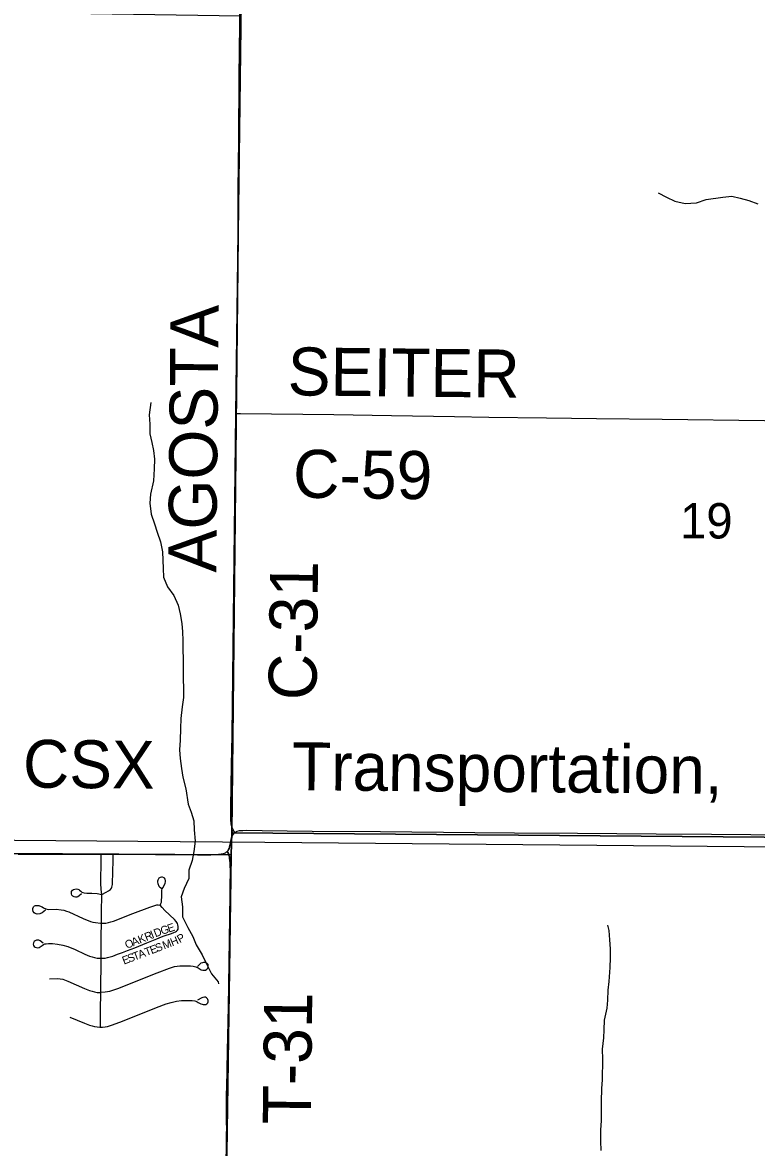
# Model space of a CAD drawing. Extents: x 1584893 to 1934202, y 663575 to 1091909.
# Drawn here: x 1743487 to 1748072, y 941008 to 948034 of the extents above; entities that cross this region are included whole.
import ezdxf

# ---------------------------------------------------------------- set-up
doc = ezdxf.new("R2010")
doc.units = 0
for name, color, linetype in [('GM_X_City_Street', 7, 'Continuous'), ('GM_X_City_Street_Text', 7, 'Continuous'), ('GM_X_Corporation', 7, 'Continuous'), ('GM_X_County_Road', 7, 'Continuous'), ('GM_X_County_Road_Text', 7, 'Continuous'), ('GM_X_Minor_River', 7, 'Continuous'), ('GM_X_Rail_Line', 7, 'Continuous'), ('GM_X_Rail_Line_Text', 7, 'Continuous'), ('GM_X_Section', 7, 'Continuous'), ('GM_X_Section_Text', 7, 'Continuous'), ('GM_X_State_Route', 7, 'Continuous'), ('GM_X_Township', 7, 'Continuous'), ('GM_X_Township_Road', 7, 'Continuous'), ('GM_X_Township_Road_Text', 7, 'Continuous')]:
    doc.layers.add(name, color=color, linetype=linetype)

msp = doc.modelspace()

# ---------------------------------------------------------------- linework, layer by layer
at = {"layer": 'GM_X_City_Street'}
for points in [[(1743982.7, 942587.2), (1743978.7, 942619.5), (1743977.2, 942658.5), (1743977.9, 942804.1), (1743978, 942841.4)], [(1743982.7, 942587.2), (1744009.9, 942601.6), (1744024.1, 942610.4), (1744031.2, 942615.2), (1744036.9, 942620), (1744042.5, 942627.1), (1744045.2, 942634), (1744047.4, 942642.1), (1744049.4, 942649.8), (1744050.5, 942666.1), (1744052.5, 942716.5), (1744052.9, 942813.3), (1744053.1, 942840.6)], [(1744348, 942521.8), (1744352.3, 942531.6), (1744355.2, 942541), (1744356.5, 942555.4), (1744356.9, 942569), (1744357.5, 942598.2), (1744358.1, 942614.6), (1744360.3, 942623.4), (1744363.5, 942629.8), (1744372.6, 942643.7), (1744378.9, 942658.8), (1744380.2, 942666.7), (1744380.2, 942674.8), (1744378.1, 942684.1), (1744375.1, 942689.2), (1744371.3, 942691.7), (1744362, 942695.2), (1744354.7, 942695.6), (1744347.5, 942694.3), (1744339.9, 942689.2), (1744334.3, 942681.5), (1744331.8, 942676.5), (1744330.5, 942671.3), (1744331, 942664.6), (1744333, 942656.5), (1744339.6, 942640.9), (1744346, 942634.6), (1744354.6, 942628.3)], [(1743856.9, 942592.7), (1743842, 942579.3), (1743833.1, 942574.3), (1743825.9, 942571.8), (1743818.7, 942571.8), (1743809.3, 942574.3), (1743801.7, 942577.3), (1743795.3, 942584.5), (1743793.2, 942591.3), (1743793.2, 942598.8), (1743794.4, 942607.5), (1743799.1, 942614.7), (1743805.5, 942618.9), (1743814.4, 942621.9), (1743822.9, 942622.8), (1743832.2, 942621.9), (1743839, 942618.5), (1743844.1, 942614.3), (1743851.4, 942608), (1743857.5, 942603.6), (1743864.5, 942600.3), (1743872.4, 942597.5), (1743888.4, 942596.1), (1743921, 942595.3), (1743953, 942593.2), (1743982.7, 942587.2)], [(1743980.6, 942409), (1743981.8, 942475.9), (1743982.7, 942587.2)], [(1743630.6, 942490.9), (1743610.5, 942474.4), (1743595.2, 942468.1), (1743578.7, 942465.9), (1743567.2, 942468.5), (1743560, 942473.1), (1743554.9, 942481.6), (1743552.7, 942492.3), (1743552.7, 942501.6), (1743556.1, 942511.4), (1743562.1, 942517.8), (1743568.5, 942519.5), (1743576.5, 942520.3), (1743588.8, 942519.9), (1743603.8, 942513.5), (1743609.2, 942510.1), (1743617.6, 942504.5), (1743632.2, 942497.6), (1743648.2, 942495.3), (1743697.3, 942495.4), (1743729.8, 942492.6), (1743745.8, 942489.5), (1743761.4, 942484.9), (1743776.6, 942479.1), (1743865.6, 942438), (1743911.2, 942420.3), (1743926.9, 942415.8), (1743942.9, 942412.6), (1743975.4, 942409.1), (1743980.6, 942409)], [(1743978, 942189.9), (1743986.8, 942189.8), (1744003.1, 942191.1), (1744019.3, 942193.9), (1744050.9, 942203.2), (1744081.6, 942214.4), (1744111.5, 942225.6), (1744143.3, 942238), (1744188.6, 942255.8), (1744265, 942286.2), (1744325.7, 942311.2), (1744356, 942323.8), (1744371.5, 942329.3), (1744418.3, 942345), (1744433.6, 942351.2), (1744442, 942354.9), (1744449.2, 942359.6), (1744455.5, 942365.1), (1744459.8, 942372.3), (1744460.6, 942380.8), (1744459.7, 942388.9), (1744458.5, 942399.1), (1744455.1, 942406.3), (1744451.3, 942412.7), (1744446.9, 942418.9), (1744436, 942431.3), (1744377.4, 942489), (1744360.3, 942507.8), (1744348, 942521.8)], [(1743980.6, 942409), (1743991.7, 942408.8), (1744008, 942409.7), (1744024.1, 942412.1), (1744039.8, 942416.3), (1744055.2, 942421.8), (1744177.1, 942468.6), (1744283, 942508.2), (1744314.8, 942519.6), (1744326.3, 942522.7), (1744335.7, 942523.1), (1744348, 942521.8)], [(1743978, 942189.9), (1743978, 942194.6), (1743979.1, 942327), (1743980.6, 942409)], [(1743617.3, 942283.4), (1743597.3, 942299.1), (1743589.3, 942302), (1743581.5, 942303.3), (1743574.5, 942303.2), (1743565.9, 942299.2), (1743560, 942294.7), (1743555.8, 942287.1), (1743554.5, 942277.7), (1743556.7, 942269.2), (1743560.9, 942262.5), (1743567.5, 942258.4), (1743574.5, 942256.1), (1743583.3, 942255.6), (1743591.9, 942257.8), (1743598.4, 942261.7), (1743609.7, 942270.5), (1743618.8, 942276.3), (1743626.3, 942279), (1743635.2, 942280.7), (1743649.7, 942282), (1743674.1, 942281.4), (1743706.9, 942277.9), (1743739.2, 942271.8), (1743770.6, 942262.3), (1743816.3, 942243.9), (1743875.8, 942215.7), (1743906.2, 942203.1), (1743921.7, 942197.7), (1743937.6, 942193.7), (1743953.9, 942191.4), (1743970.3, 942190), (1743978, 942189.9)], [(1743977, 941977.1), (1743977.1, 941979.2), (1743978, 942189.9)], [(1743977, 941977.1), (1744003.9, 941979.3), (1744032.5, 941984.3), (1744052.2, 941989.7), (1744083.2, 942001.2), (1744328.9, 942098.9), (1744406.1, 942128.2), (1744437.7, 942137.6), (1744453.9, 942140.6), (1744470.3, 942142.4), (1744503.4, 942143.1), (1744536.5, 942141.9), (1744552.9, 942140.2), (1744569, 942136.7), (1744583.8, 942129.7), (1744598, 942121), (1744604.3, 942117.9), (1744613.4, 942115.4), (1744622.6, 942115.4), (1744631.1, 942116.2), (1744639.1, 942120.9), (1744645.1, 942127.2), (1744647.2, 942134.9), (1744648, 942142.6), (1744646.3, 942151.5), (1744641.7, 942157.9), (1744633.2, 942162.1), (1744626, 942163.1), (1744618.3, 942162.9), (1744611.1, 942161.2), (1744602.2, 942158.3), (1744580.3, 942139.4)], [(1743656.8, 942060.5), (1743706.3, 942062.7), (1743722.7, 942061.7), (1743738.7, 942058.3), (1743769.8, 942047.5), (1743875.6, 942000.4), (1743906.4, 941988.4), (1743922.1, 941983.4), (1743938.1, 941979.2), (1743954.4, 941976.9), (1743970.9, 941976.5), (1743977, 941977.1)], [(1743974.9, 941760.5), (1743975, 941770.2), (1743975.4, 941863.2), (1743977, 941977.1)], [(1743974.9, 941760.5), (1743986.5, 941760.4), (1744002.8, 941761.8), (1744018.9, 941764.6), (1744050.4, 941773.4), (1744111.8, 941796.1), (1744324, 941882.7), (1744385.4, 941905.3), (1744416.8, 941914.3), (1744448.8, 941921.1), (1744481.3, 941925.3), (1744514, 941927), (1744546.7, 941925.8), (1744562.9, 941923.4), (1744571, 941921.1), (1744578.4, 941918.6), (1744585.3, 941914.5), (1744592.4, 941910.1), (1744601.2, 941906), (1744609.1, 941903.5), (1744615.4, 941901.3), (1744623.1, 941900.1), (1744632.1, 941901), (1744639.3, 941904.8), (1744644.3, 941910.6), (1744646.7, 941918.6), (1744646.8, 941926.6), (1744646, 941932), (1744643.4, 941937.4), (1744637.6, 941943.3), (1744630.9, 941946.2), (1744623.8, 941946.6), (1744614.2, 941945), (1744607.4, 941942.4), (1744579.6, 941927.2)], [(1743783.3, 941822.5), (1743875.4, 941784), (1743906, 941772.3), (1743921.7, 941767.7), (1743937.7, 941764.2), (1743953.8, 941761.8), (1743970.2, 941760.5), (1743974.9, 941760.5)]]:
    msp.add_lwpolyline(points, dxfattribs=at)
at = {"layer": 'GM_X_Corporation'}
msp.add_lwpolyline([(1743460.5, 942839), (1743978, 942839.2), (1744053.1, 942839.5), (1744637.5, 942836.5), (1744662.8, 942836.4), (1744712.1, 942839), (1744723.3, 942840.1), (1744730.1, 942841.3), (1744736.8, 942842.5), (1744743.4, 942844.5), (1744749.6, 942847), (1744754.5, 942849), (1744759.2, 942851.6), (1744762.5, 942854.1), (1744767.1, 942857.6), (1744770.9, 942850.5), (1744774, 942843), (1744777.1, 942833.5), (1744779.8, 942822.2), (1744781.1, 942813.5), (1744782.4, 942801.8), (1744783, 942795.8), (1744783.6, 942789.8), (1744784.2, 942777.5), (1744784.5, 942769.2), (1744785.8, 942726.7), (1744748.2, 940195)], dxfattribs=at)
at = {"layer": 'GM_X_County_Road'}
for points in [[(1744824.3, 945591.8), (1744824.3, 945594.2), (1744825.3, 945791.2), (1744828.5, 946070.1), (1744832, 946513.2), (1744835, 946775.6), (1744835, 946989), (1744838.4, 947300.7), (1744841.1, 947694.6), (1744845.9, 948186.9), (1744850.1, 948433), (1744853.9, 948580.6), (1744855.8, 948777.5), (1744859, 948941.5), (1744860.9, 949122), (1744870.2, 949614.2), (1744873.8, 949893.1), (1744876.9, 950122.8), (1744883.5, 950434.6), (1744889.1, 950680.5), (1744889.8, 950741.2)], [(1744813.7, 942974.7), (1744803.1, 942990.9), (1744794.4, 943011.2), (1744791, 943029.2), (1744790.1, 943038.7), (1744789.4, 943046.8), (1744789.4, 943133.2), (1744793.6, 943395.8), (1744799.4, 943674.7), (1744802.7, 943838.6), (1744803.6, 944002.7), (1744807.7, 944248.8), (1744816.3, 944839.5), (1744822, 945331.7), (1744824.3, 945591.8)], [(1744824.3, 945591.8), (1744849.5, 945591.5), (1745431.6, 945584.6), (1745792.6, 945579.5), (1746186.4, 945572.6), (1746399.8, 945569.5), (1746760.7, 945563.8), (1747072.5, 945561), (1747482.8, 945556.3), (1748122.9, 945548.9), (1748303.3, 945545.8), (1748615.2, 945542.8), (1748894.1, 945539.7), (1749140.3, 945537.2), (1749567, 945533.7), (1750042.9, 945528), (1750371.1, 945523.8), (1750929, 945521.9), (1751618.3, 945526), (1751930.1, 945525.6), (1752043.2, 945526.4)]]:
    msp.add_lwpolyline(points, dxfattribs=at)
at = {"layer": 'GM_X_Minor_River'}
for points in [[(1747457.4, 946969), (1747509, 946942.1), (1747562.7, 946917.2), (1747626.5, 946904.1), (1747696.7, 946906.9), (1747757.1, 946928), (1747861.5, 946942.3), (1747917.6, 946949.4), (1747969.5, 946936.5), (1748023.3, 946921.6), (1748081, 946900.6)], [(1744288, 945659.7), (1744278.8, 945583.7), (1744281.8, 945525.5), (1744282.8, 945465.4), (1744295.9, 945411), (1744305.1, 945360.8), (1744312.2, 945306.5), (1744309.2, 945246.4), (1744306, 945172.3), (1744286.6, 945088.4), (1744283.7, 945032.4), (1744290.6, 944964.1), (1744311.6, 944903.6), (1744328.8, 944851.2), (1744349.8, 944790.7), (1744360.8, 944728.4), (1744363.9, 944676.2), (1744365.1, 944624.1), (1744368.2, 944569.9), (1744393.2, 944509.4), (1744432.4, 944454.6), (1744459.4, 944394), (1744472.6, 944341.7), (1744481.6, 944281.4), (1744486.7, 944229.2), (1744487.8, 944175.1), (1744488.9, 944118.9), (1744489.9, 944056.7), (1744490.9, 943996.6), (1744491.9, 943932.4), (1744492.9, 943876.3), (1744492, 943818.2), (1744485, 943760.1), (1744475.8, 943686.1), (1744474.8, 943624), (1744471.6, 943551.9), (1744468.6, 943491.8), (1744471.7, 943437.6), (1744480.7, 943375.3), (1744489.8, 943321), (1744506.6, 943248.6), (1744521.1, 943152.1), (1744540.3, 943101.7), (1744557.4, 943047.3), (1744560.5, 942991.1), (1744565.3, 942920.9), (1744558.3, 942856.8), (1744547.3, 942800.9), (1744526.3, 942739.1), (1744525.4, 942687), (1744496.4, 942625.3), (1744477.5, 942573.5), (1744486.5, 942511.2), (1744487.5, 942449), (1744520.4, 942382.3), (1744551.5, 942325.7), (1744572.7, 942273.2), (1744609.7, 942210.5), (1744636.8, 942155.9), (1744667.9, 942093.3), (1744709.1, 942042.5), (1744710.9, 942030.4)], [(1747102.6, 940988.8), (1747099.6, 941047), (1747100.7, 941117.2), (1747103.7, 941177.3), (1747104.7, 941237.4), (1747103.7, 941295.6), (1747105, 941375.7), (1747109.9, 941429.8), (1747112, 941560.1), (1747111, 941622.2), (1747118.2, 941692.3), (1747121, 941742.3), (1747122, 941802.5), (1747139.3, 941878.4), (1747144.1, 941928.4), (1747145.1, 941990.5), (1747152, 942044.5), (1747157.5, 942132.7), (1747160.5, 942192.8), (1747159.4, 942248.9), (1747156.3, 942305.1), (1747151.3, 942363.3), (1747143.8, 942395.5)]]:
    msp.add_lwpolyline(points, dxfattribs=at)
at = {"layer": 'GM_X_Rail_Line'}
msp.add_lwpolyline([(1729199.1, 942645.5), (1729331.6, 942693.1), (1729485.4, 942744.4), (1729623.9, 942788.6), (1729792.4, 942836.9), (1729977.3, 942881.6), (1730117.6, 942911.7), (1730271.9, 942940.6), (1730423.3, 942964.1), (1730534.1, 942980.6), (1730661.9, 942994.8), (1730835.8, 943008.9), (1730988.9, 943017.7), (1731122.7, 943022.5), (1731285.9, 943023), (1731992.3, 943018.9), (1733508.2, 943007.1), (1736702.6, 942983), (1740093.8, 942954.7), (1742156.4, 942937.6), (1744208.5, 942921.7), (1745001.5, 942915.2), (1747995.6, 942888.1), (1750152.5, 942869.9)], dxfattribs=at)
at = {"layer": 'GM_X_Section'}
for points in [[(1744852.8, 948192.1), (1750761, 948123.4), (1750676.5, 942925.4), (1744794.1, 942974), (1744849.8, 948076.2)], [(1739635.8, 948156.7), (1744849.8, 948076.2), (1744794.1, 942974), (1744790.8, 942835.4), (1739520.5, 942867.1)], [(1744794.1, 942974), (1750676.5, 942925.4), (1750594.8, 937603.3), (1744716.7, 937672), (1744790.8, 942835.4)], [(1739520.5, 942867.1), (1744790.8, 942835.4), (1744716.7, 937672), (1744713.4, 937535.9), (1741403.5, 937589.6), (1739430.9, 937549.2)]]:
    msp.add_lwpolyline(points, close=True, dxfattribs=at)
at = {"layer": 'GM_X_State_Route'}
for points in [[(1744767.1, 942857.6), (1744771.3, 942862.7), (1744775.1, 942868.5), (1744778.2, 942875.5), (1744780.2, 942882.4), (1744786, 942908.1), (1744790.7, 942934.1), (1744795.1, 942949.5), (1744804.1, 942963.5), (1744813.7, 942974.7), (1744827.4, 942982.8), (1744842.7, 942986.9), (1744863.5, 942988.4), (1744884.3, 942989), (1744984.8, 942987.6), (1745296.5, 942984.4), (1745722.9, 942980.6), (1746313.6, 942975.7), (1746559.7, 942973.8), (1746953.4, 942970.2), (1747445.6, 942966.3), (1747790.2, 942965.1), (1748036.2, 942963.4), (1748594, 942958)], [(1743463.8, 942842.9), (1743680.1, 942841.8), (1743958.5, 942841.6), (1743978, 942841.4), (1744053.1, 942840.6), (1744580.8, 942835.5), (1744662.8, 942836.4), (1744712.1, 942839), (1744723.3, 942840.1), (1744736.8, 942842.5), (1744743.5, 942844.5), (1744749.7, 942847), (1744754.5, 942849), (1744759.2, 942851.6), (1744762.5, 942854.1), (1744767.1, 942857.6)]]:
    msp.add_lwpolyline(points, dxfattribs=at)
at = {"layer": 'GM_X_Township'}
for points in [[(1744748.2, 940195), (1744785.8, 942726.7), (1744784.2, 942777.5), (1744783.6, 942789.8), (1744783, 942795.8), (1744782.4, 942801.8), (1744781.6, 942808.7), (1744781.1, 942813.5), (1744779.8, 942822.2), (1744777.1, 942833.5), (1744774, 942843), (1744772.5, 942846.8), (1744770.9, 942850.5), (1744767.1, 942857.6), (1744771.3, 942862.7), (1744775.1, 942868.5), (1744778.2, 942875.5), (1744780.2, 942882.4), (1744780.7, 942885.7), (1744786, 942908.1), (1744790.7, 942934.1), (1744796.8, 942953.5), (1744794.4, 943011.2), (1744790.1, 943038.7), (1744819.2, 945590.6), (1744886.9, 950744.1)], [(1744886.9, 950744.1), (1744819.2, 945590.6), (1744790.1, 943038.7), (1744794.4, 943011.2), (1744796.8, 942953.5), (1744790.7, 942934.1), (1744786, 942908.1), (1744780.7, 942885.7), (1744780.2, 942882.4), (1744778.2, 942875.5), (1744775.1, 942868.5), (1744771.3, 942862.7), (1744767.1, 942857.6), (1744770.9, 942850.5), (1744772.5, 942846.8), (1744774, 942843), (1744777.1, 942833.5), (1744779.8, 942822.2), (1744781.1, 942813.5), (1744781.6, 942808.7), (1744782.4, 942801.8), (1744783, 942795.8), (1744783.6, 942789.8), (1744784.2, 942777.5), (1744785.8, 942726.7), (1744748.2, 940195)]]:
    msp.add_lwpolyline(points, dxfattribs=at)
at = {"layer": 'GM_X_Township_Road'}
for points in [[(1744763, 941380.5), (1744766.8, 941608.7), (1744775.1, 941888.5), (1744777.2, 942036.7), (1744780, 942316.6), (1744783.5, 942481.2), (1744785.2, 942645.9), (1744785.7, 942728.2), (1744784.2, 942777.5), (1744783.6, 942789.8), (1744782.4, 942801.8), (1744781.1, 942813.5), (1744779.8, 942822.2), (1744777.1, 942833.5), (1744774, 942843), (1744770.9, 942850.5), (1744767.1, 942857.6)], [(1744762, 941147.9), (1744762.4, 941345.3), (1744763, 941380.5)]]:
    msp.add_lwpolyline(points, dxfattribs=at)

# ---------------------------------------------------------------- texts
at = {"layer": 'GM_X_City_Street_Text'}
for s, rotation, p in [('E', 18.60055, (1744401.1, 942349.6)), ('K', 21.88664, (1744220.3, 942280.6)), ('R', 21.87808, (1744261.1, 942297)), ('I', 21.90162, (1744297.9, 942311.8)), ('D', 21.87851, (1744318.3, 942320)), ('G', 17.56396, (1744358.2, 942336)), ('P', 29.51034, (1744469.9, 942283.3)), ('O', 21.87851, (1744138.6, 942247.8)), ('A', 21.86602, (1744179.4, 942264.2)), ('T', 20.62958, (1744260.8, 942202.6)), ('E', 20.64686, (1744293.8, 942215)), ('S', 20.62958, (1744326.7, 942227.4)), ('M', 20.77151, (1744372.1, 942244.5)), ('H', 22.00204, (1744422.6, 942263.7)), ('E', 20.62958, (1744120.8, 942149.9)), ('S', 20.63138, (1744153.7, 942162.3)), ('T', 20.64686, (1744186.7, 942174.7)), ('A', 20.651, (1744219.7, 942187.1))]:
    msp.add_text(s, height=50, rotation=rotation, dxfattribs=at).set_placement(p)
at = {"layer": 'GM_X_County_Road_Text'}
for s, rotation, p in [('AGOSTA', 89.49456, (1744697.3, 944598.3)), ('SEITER', 359.39177, (1745142.6, 945705.5)), ('C-59', 359.31264, (1745176.1, 945066.4)), ('C-31', 89.31129, (1745323.4, 943800.2))]:
    msp.add_text(s, height=300, rotation=rotation, dxfattribs=at).set_placement(p)
at = {"layer": 'GM_X_Rail_Line_Text'}
for s, rotation, p in [('CSX', 359.46979, (1743489.5, 943255.8)), ('Transportation,', 359.50319, (1745170.2, 943239.9))]:
    msp.add_text(s, height=299, rotation=rotation, dxfattribs=at).set_placement(p)
at = {"layer": 'GM_X_Section_Text'}
msp.add_text('19', height=221, rotation=0.00001, dxfattribs=at).set_placement((1747594, 944811.2))
at = {"layer": 'GM_X_Township_Road_Text'}
msp.add_text('T-31', height=300, rotation=89.2917, dxfattribs=at).set_placement((1745287.6, 941150.3))

doc.saveas('drawing.dxf')
